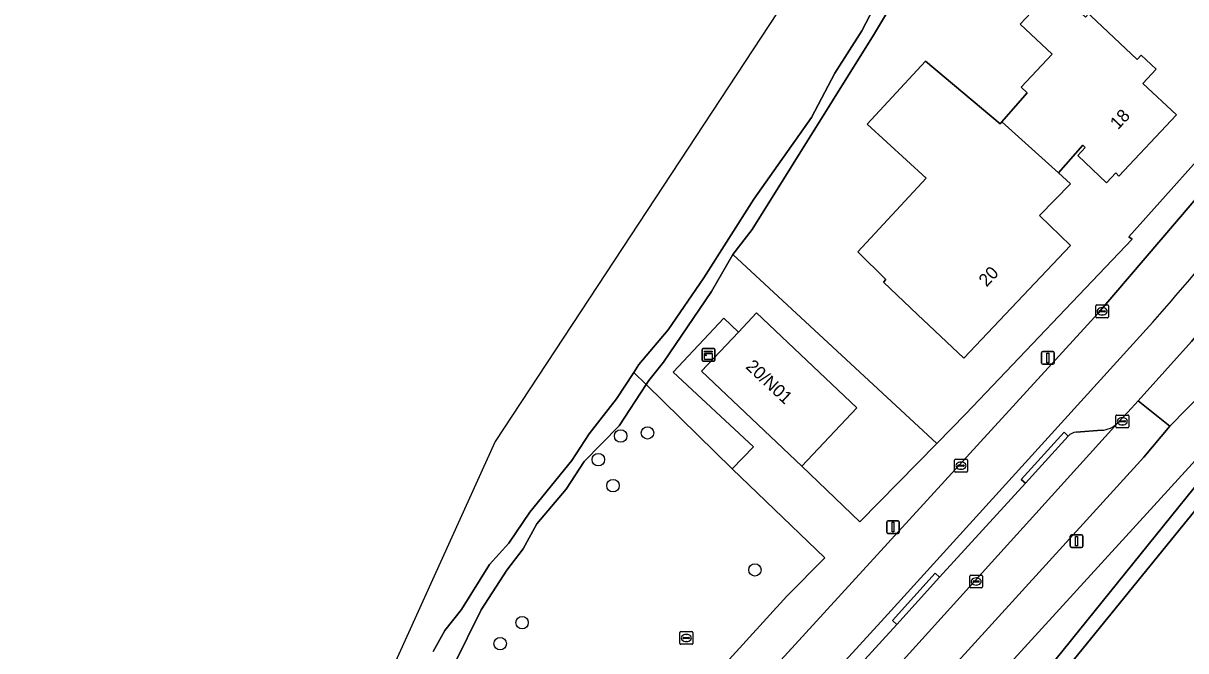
# Model space of a CAD drawing. Extents: x 161772 to 163126, y 383092 to 383917.
# Drawn here: x 161850.9 to 161942.3, y 383268.9 to 383318.3 of the extents above; entities that cross this region are included whole.
import ezdxf

# ---------------------------------------------------------------- set-up
doc = ezdxf.new("R2010")
doc.units = 0
for name, color, linetype in [('IMGEO_Berm_open', 7, 'Continuous'), ('IMGEO_Boom', 7, 'Continuous'), ('IMGEO_Erf', 7, 'Continuous'), ('IMGEO_Fietspad_gesloten', 7, 'Continuous'), ('IMGEO_Groenvoorziening', 7, 'Continuous'), ('IMGEO_Hek', 7, 'Continuous'), ('IMGEO_Kast', 7, 'Continuous'), ('IMGEO_Kolk', 7, 'Continuous'), ('IMGEO_Lichtmast', 7, 'Continuous'), ('IMGEO_Oever', 7, 'Continuous'), ('IMGEO_Pand', 7, 'Continuous'), ('IMGEO_Pand_nummerreeks', 7, 'Continuous'), ('IMGEO_Parkeervlak_open', 7, 'Continuous'), ('IMGEO_Rijbaan_lokaal_gesloten', 7, 'Continuous'), ('IMGEO_Rioolput', 7, 'Continuous'), ('IMGEO_Voetpad_halfverhard', 7, 'Continuous'), ('IMGEO_Voetpad_open', 7, 'Continuous'), ('IMGEO_Waterloop', 7, 'Continuous')]:
    doc.layers.add(name, color=color, linetype=linetype)

msp = doc.modelspace()

# ---------------------------------------------------------------- linework, layer by layer
at = {"layer": 'IMGEO_Berm_open'}
for points in [[(161936.941, 383286.844), (161937.725, 383287.694), (161938.545, 383288.593), (161942.733, 383293.261), (161946.965, 383298.168), (161951.858, 383304.076), (161955.895, 383309.039), (161956.93, 383310.332), (161955.277, 383311.727), (161955.257, 383311.744), (161958.985, 383316.324), (161961.426, 383319.531), (161961.064, 383319.803), (161964.615, 383324.66), (161964.958, 383324.39), (161966.144, 383326.081)], [(161939.704, 383294.768), (161918.598, 383271.518), (161889.95, 383240.214)], [(161891.178, 383239.989), (161919.558, 383271.008), (161919.229, 383271.314), (161922.593, 383275.04), (161922.916, 383274.718), (161929.677, 383282.101), (161929.346, 383282.406), (161932.714, 383286.12), (161933.044, 383285.816)], [(161933.657, 383286.132), (161935.675, 383286.268)]]:
    msp.add_lwpolyline(points, dxfattribs=at)
for points in [[(161933.044, 383285.816), (161932.714, 383286.12), (161929.346, 383282.406), (161929.677, 383282.101)], [(161922.916, 383274.718), (161922.593, 383275.04), (161919.229, 383271.314), (161919.558, 383271.008)]]:
    msp.add_lwpolyline(points, close=True, dxfattribs=at)
for centre, radius, start, end in [((161591.388, 383599.05), 462.506, 318.86018, 321.05072), ((161935.529, 383288.269), 2.006, 274.18246, 314.74636), ((161933.804, 383285.094), 1.048, 98.05832, 136.48367)]:
    msp.add_arc(centre, radius, start, end, dxfattribs=at)
at = {"layer": 'IMGEO_Boom'}
for centre in [(161897.856, 383285.821), (161899.96, 383286.062), (161896.094, 383283.96), (161897.255, 383281.917), (161908.41, 383275.292), (161890.104, 383271.15), (161888.379, 383269.494)]:
    msp.add_circle(centre, 0.489, dxfattribs=at)
at = {"layer": 'IMGEO_Erf'}
for points in [[(161924.879, 383329.289), (161917.722, 383317.318), (161908.185, 383302.04), (161906.674, 383300.084), (161904.997, 383297.167), (161901.213, 383291.611), (161900.058, 383290.19), (161899.854, 383289.876), (161906.619, 383283.229), (161908.3, 383284.957), (161901.974, 383290.839), (161905.957, 383295.079), (161907.106, 383293.995), (161908.521, 383295.495), (161916.425, 383288.039), (161912.104, 383283.459), (161916.662, 383279.077), (161922.701, 383285.219), (161925, 383287.557), (161938.061, 383301.283), (161937.818, 383301.48), (161946.008, 383310.656), (161948.264, 383313.526), (161954.519, 383321.774)], [(161934.812, 383318.85), (161938.454, 383315.424), (161938.769, 383315.758), (161939.954, 383314.644), (161938.912, 383313.536), (161941.548, 383311.055), (161937.034, 383306.258), (161936.778, 383306.499), (161936.057, 383305.732), (161933.79, 383307.865), (161934.388, 383308.5), (161934.191, 383308.685), (161932.283, 383306.506), (161933.226, 383305.654), (161930.788, 383303.163), (161933.215, 383300.787), (161924.825, 383291.929), (161921.195, 383295.367), (161918.509, 383297.912), (161918.702, 383298.116), (161916.489, 383300.309), (161921.863, 383306.099), (161917.248, 383310.333), (161921.833, 383315.278), (161927.696, 383310.365), (161927.822, 383310.509), (161929.823, 383312.795), (161929.343, 383313.247), (161931.775, 383315.831), (161929.259, 383318.198), (161931.93, 383321.045)]]:
    msp.add_lwpolyline(points, dxfattribs=at)
at = {"layer": 'IMGEO_Fietspad_gesloten'}
for points in [[(161953.961, 383317.758), (161942.798, 383304.121), (161935.389, 383295.477), (161886.612, 383242.159)], [(161889.95, 383240.214), (161918.598, 383271.518), (161939.704, 383294.768)]]:
    msp.add_lwpolyline(points, dxfattribs=at)
msp.add_arc((161591.388, 383599.05), 462.506, 318.86018, 321.05072, dxfattribs=at)
at = {"layer": 'IMGEO_Groenvoorziening'}
for points in [[(161886.411, 383246.323), (161910.93, 383273.227), (161913.897, 383276.251), (161906.619, 383283.229), (161899.854, 383289.876), (161897.734, 383286.618), (161894.983, 383283.813), (161893.566, 383281.629), (161891.274, 383278.907), (161890.193, 383276.947), (161888.911, 383275.275), (161886.883, 383272.166), (161884.708, 383267.756), (161883.189, 383265.632), (161882.266, 383263.994), (161881.616, 383259.978), (161879.669, 383255.592), (161877.612, 383250), (161876.974, 383248.266), (161883.313, 383242.582)], [(161920.997, 383254.575), (161919.034, 383256.173), (161924.881, 383263.332), (161926.722, 383261.652), (161947.115, 383286.904)], [(161944.99, 383286.04), (161914.219, 383252.347), (161915.758, 383251.09), (161917.095, 383249.921), (161920.997, 383254.575)]]:
    msp.add_lwpolyline(points, dxfattribs=at)
at = {"layer": 'IMGEO_Hek'}
msp.add_lwpolyline([(161906.674, 383300.084), (161922.701, 383285.219)], dxfattribs=at)
at = {"layer": 'IMGEO_Kast'}
for p, q in [((161904.336, 383292.699), (161905.177, 383292.699)), ((161905.177, 383292.699), (161904.336, 383292.699)), ((161904.261, 383291.774), (161904.261, 383292.615)), ((161904.261, 383292.615), (161904.261, 383291.774)), ((161905.261, 383292.624), (161905.261, 383291.783)), ((161905.261, 383291.783), (161905.261, 383292.624)), ((161905.186, 383291.699), (161904.345, 383291.699)), ((161904.345, 383291.699), (161905.186, 383291.699))]:
    msp.add_line(p, q, dxfattribs=at)
for points in [[(161904.456, 383292.489), (161905.056, 383292.489), (161905.056, 383292.404), (161904.456, 383292.404), (161904.456, 383292.489)], [(161904.456, 383292.314), (161905.056, 383292.314), (161905.056, 383291.825), (161904.456, 383291.825), (161904.456, 383292.314)]]:
    msp.add_lwpolyline(points, dxfattribs=at)
msp.add_circle((161904.54, 383292.163), 0.0377, dxfattribs=at)
for centre, start, end in [((161904.339, 383292.621), 92.4484, 184.28452), ((161904.339, 383292.621), 92.4484, 184.28452), ((161905.183, 383292.621), 2.4484, 94.28452), ((161905.183, 383292.621), 2.4484, 94.28452), ((161905.183, 383291.777), 272.4484, 4.28452), ((161905.183, 383291.777), 272.4484, 4.28452), ((161904.339, 383291.777), 182.4484, 274.28452), ((161904.339, 383291.777), 182.4484, 274.28452)]:
    msp.add_arc(centre, 0.0779, start, end, dxfattribs=at)
at = {"layer": 'IMGEO_Kolk'}
for p, q in [((161935.215, 383295.192), (161935.215, 383296.044)), ((161935.29, 383296.118), (161936.142, 383296.118)), ((161935.474, 383295.612), (161935.474, 383295.624)), ((161935.912, 383295.575), (161935.514, 383295.575)), ((161935.517, 383295.661), (161935.915, 383295.661)), ((161935.703, 383295.898), (161935.728, 383295.898)), ((161935.958, 383295.624), (161935.958, 383295.612)), ((161936.216, 383296.044), (161936.216, 383295.192)), ((161936.142, 383295.118), (161935.29, 383295.118)), ((161935.726, 383295.338), (161935.701, 383295.338)), ((161936.799, 383286.544), (161936.799, 383287.396)), ((161936.874, 383287.47), (161937.726, 383287.47)), ((161937.287, 383287.25), (161937.312, 383287.25)), ((161937.8, 383287.396), (161937.8, 383286.544)), ((161937.726, 383286.47), (161936.874, 383286.47)), ((161937.058, 383286.964), (161937.058, 383286.976)), ((161937.496, 383286.927), (161937.098, 383286.927)), ((161937.101, 383287.013), (161937.499, 383287.013)), ((161937.31, 383286.69), (161937.285, 383286.69)), ((161937.542, 383286.976), (161937.542, 383286.964)), ((161924.11, 383283.061), (161924.11, 383283.913)), ((161924.185, 383283.987), (161925.037, 383283.987)), ((161924.598, 383283.767), (161924.623, 383283.767)), ((161925.111, 383283.913), (161925.111, 383283.061)), ((161925.037, 383282.987), (161924.185, 383282.987)), ((161924.369, 383283.481), (161924.369, 383283.493)), ((161924.807, 383283.444), (161924.409, 383283.444)), ((161924.412, 383283.53), (161924.81, 383283.53)), ((161924.621, 383283.207), (161924.596, 383283.207)), ((161924.853, 383283.493), (161924.853, 383283.481)), ((161925.308, 383273.955), (161925.308, 383274.807)), ((161925.383, 383274.881), (161926.235, 383274.881)), ((161925.61, 383274.424), (161926.008, 383274.424)), ((161925.796, 383274.661), (161925.821, 383274.661)), ((161926.309, 383274.807), (161926.309, 383273.955)), ((161926.235, 383273.881), (161925.383, 383273.881)), ((161925.567, 383274.375), (161925.567, 383274.387)), ((161926.005, 383274.338), (161925.607, 383274.338)), ((161925.819, 383274.101), (161925.794, 383274.101)), ((161926.051, 383274.387), (161926.051, 383274.375))]:
    msp.add_line(p, q, dxfattribs=at)
for points in [[(161935.215, 383295.192), (161935.215, 383296.044)], [(161935.29, 383296.118), (161936.142, 383296.118)], [(161936.216, 383296.044), (161936.216, 383295.192)], [(161936.142, 383295.118), (161935.29, 383295.118)], [(161936.799, 383286.544), (161936.799, 383287.396)], [(161936.874, 383287.47), (161937.726, 383287.47)], [(161937.8, 383287.396), (161937.8, 383286.544)], [(161937.726, 383286.47), (161936.874, 383286.47)], [(161924.11, 383283.061), (161924.11, 383283.913)], [(161924.185, 383283.987), (161925.037, 383283.987)], [(161925.111, 383283.913), (161925.111, 383283.061)], [(161925.037, 383282.987), (161924.185, 383282.987)], [(161925.308, 383273.955), (161925.308, 383274.807)], [(161925.383, 383274.881), (161926.235, 383274.881)], [(161926.309, 383274.807), (161926.309, 383273.955)], [(161926.235, 383273.881), (161925.383, 383273.881)]]:
    msp.add_lwpolyline(points, dxfattribs=at)
for centre, radius, start, end in [((161935.292, 383296.042), 0.0765, 91.55205, 178.44795), ((161935.292, 383296.042), 0.0765, 91.55205, 178.44795), ((161935.514, 383295.621), 0.0403, 85.87752, 175.75265), ((161935.511, 383295.611), 0.0366, 178.93798, 274.71019), ((161935.915, 383295.618), 0.043, 264.86636, 352.45326), ((161935.919, 383295.623), 0.0386, 1.73085, 96.63898), ((161936.14, 383296.042), 0.0765, 1.55205, 88.44795), ((161936.14, 383296.042), 0.0765, 1.55205, 88.44795), ((161935.292, 383295.194), 0.0765, 181.55205, 268.44795), ((161935.292, 383295.194), 0.0765, 181.55205, 268.44795), ((161936.14, 383295.194), 0.0765, 271.55205, 358.44795), ((161936.14, 383295.194), 0.0765, 271.55205, 358.44795), ((161936.876, 383287.394), 0.0765, 91.55205, 178.44795), ((161936.876, 383287.394), 0.0765, 91.55205, 178.44795), ((161937.724, 383287.394), 0.0765, 1.55205, 88.44795), ((161937.724, 383287.394), 0.0765, 1.55205, 88.44795), ((161936.876, 383286.546), 0.0765, 181.55205, 268.44795), ((161936.876, 383286.546), 0.0765, 181.55205, 268.44795), ((161937.098, 383286.973), 0.0403, 85.87752, 175.75265), ((161937.095, 383286.963), 0.0366, 178.93798, 274.71019), ((161937.499, 383286.97), 0.043, 264.86636, 352.45326), ((161937.503, 383286.975), 0.0386, 1.73085, 96.63898), ((161937.724, 383286.546), 0.0765, 271.55205, 358.44795), ((161937.724, 383286.546), 0.0765, 271.55205, 358.44795), ((161924.187, 383283.911), 0.0765, 91.55205, 178.44795), ((161924.187, 383283.911), 0.0765, 91.55205, 178.44795), ((161925.035, 383283.911), 0.0765, 1.55205, 88.44795), ((161925.035, 383283.911), 0.0765, 1.55205, 88.44795), ((161924.187, 383283.063), 0.0765, 181.55205, 268.44795), ((161924.187, 383283.063), 0.0765, 181.55205, 268.44795), ((161924.409, 383283.49), 0.0403, 85.87752, 175.75265), ((161924.406, 383283.48), 0.0366, 178.93798, 274.71019), ((161924.81, 383283.487), 0.043, 264.86636, 352.45326), ((161924.814, 383283.492), 0.0386, 1.73085, 96.63898), ((161925.035, 383283.063), 0.0765, 271.55205, 358.44795), ((161925.035, 383283.063), 0.0765, 271.55205, 358.44795), ((161925.385, 383274.805), 0.0765, 91.55205, 178.44795), ((161925.385, 383274.805), 0.0765, 91.55205, 178.44795), ((161925.607, 383274.384), 0.0403, 85.87752, 175.75265), ((161926.012, 383274.386), 0.0386, 1.73085, 96.63898), ((161926.233, 383274.805), 0.0765, 1.55205, 88.44795), ((161926.233, 383274.805), 0.0765, 1.55205, 88.44795), ((161925.385, 383273.957), 0.0765, 181.55205, 268.44795), ((161925.385, 383273.957), 0.0765, 181.55205, 268.44795), ((161925.604, 383274.374), 0.0366, 178.93798, 274.71019), ((161926.008, 383274.381), 0.043, 264.86636, 352.45326), ((161926.233, 383273.957), 0.0765, 271.55205, 358.44795), ((161926.233, 383273.957), 0.0765, 271.55205, 358.44795)]:
    msp.add_arc(centre, radius, start, end, dxfattribs=at)
for centre, major_axis, ratio, start_param, end_param in [((161935.702, 383295.618), (-0.387, 0.002), 0.722429, 4.712389, 7.853982), ((161935.727, 383295.618), (-0.39, 0.002), 0.717154, 1.570796, 4.712389), ((161937.286, 383286.97), (-0.387, 0.002), 0.722429, 4.712389, 7.853982), ((161937.311, 383286.97), (-0.39, 0.002), 0.717154, 1.570796, 4.712389), ((161924.597, 383283.487), (-0.387, 0.002), 0.722429, 4.712389, 7.853982), ((161924.622, 383283.487), (-0.39, 0.002), 0.717154, 1.570796, 4.712389), ((161925.795, 383274.381), (-0.387, 0.002), 0.722429, 4.712389, 7.853982), ((161925.82, 383274.381), (-0.39, 0.002), 0.717154, 1.570796, 4.712389)]:
    msp.add_ellipse(centre, major_axis=major_axis, ratio=ratio, start_param=start_param, end_param=end_param, dxfattribs=at)
at = {"layer": 'IMGEO_Lichtmast'}
for p, q in [((161930.945, 383291.556), (161930.945, 383292.356)), ((161930.945, 383292.356), (161930.945, 383291.556)), ((161931.045, 383292.456), (161931.835, 383292.456)), ((161931.835, 383292.456), (161931.045, 383292.456)), ((161931.935, 383292.356), (161931.935, 383291.556)), ((161931.935, 383291.556), (161931.935, 383292.356)), ((161931.835, 383291.456), (161931.045, 383291.456)), ((161931.045, 383291.456), (161931.835, 383291.456)), ((161918.771, 383278.262), (161918.771, 383279.062)), ((161918.771, 383279.062), (161918.771, 383278.262)), ((161918.871, 383279.162), (161919.661, 383279.162)), ((161919.661, 383279.162), (161918.871, 383279.162)), ((161919.761, 383279.062), (161919.761, 383278.262)), ((161919.761, 383278.262), (161919.761, 383279.062)), ((161919.661, 383278.162), (161918.871, 383278.162)), ((161918.871, 383278.162), (161919.661, 383278.162)), ((161933.208, 383277.15), (161933.208, 383277.95)), ((161933.208, 383277.95), (161933.208, 383277.15)), ((161933.308, 383278.05), (161934.098, 383278.05)), ((161934.098, 383278.05), (161933.308, 383278.05)), ((161934.198, 383277.95), (161934.198, 383277.15)), ((161934.198, 383277.15), (161934.198, 383277.95)), ((161934.098, 383277.05), (161933.308, 383277.05)), ((161933.308, 383277.05), (161934.098, 383277.05))]:
    msp.add_line(p, q, dxfattribs=at)
for points in [[(161931.365, 383292.331), (161931.515, 383292.331), (161931.515, 383291.581), (161931.365, 383291.581), (161931.365, 383292.331)], [(161919.191, 383279.037), (161919.341, 383279.037), (161919.341, 383278.287), (161919.191, 383278.287), (161919.191, 383279.037)], [(161933.628, 383277.925), (161933.778, 383277.925), (161933.778, 383277.175), (161933.628, 383277.175), (161933.628, 383277.925)]]:
    msp.add_lwpolyline(points, dxfattribs=at)
for centre, start, end in [((161931.045, 383292.356), 90, 180), ((161931.045, 383292.356), 90, 180), ((161931.835, 383292.356), 0, 90), ((161931.835, 383292.356), 360, 90), ((161931.045, 383291.556), 180, 270), ((161931.045, 383291.556), 180, 270), ((161931.835, 383291.556), 270, 0), ((161931.835, 383291.556), 270, 0), ((161918.871, 383279.062), 90, 180), ((161918.871, 383279.062), 90, 180), ((161919.661, 383279.062), 0, 90), ((161919.661, 383279.062), 360, 90), ((161918.871, 383278.262), 180, 270), ((161918.871, 383278.262), 180, 270), ((161919.661, 383278.262), 270, 0), ((161919.661, 383278.262), 270, 0), ((161933.308, 383277.95), 90, 180), ((161933.308, 383277.95), 90, 180), ((161933.308, 383277.15), 180, 270), ((161933.308, 383277.15), 180, 270), ((161934.098, 383277.95), 0, 90), ((161934.098, 383277.95), 360, 90), ((161934.098, 383277.15), 270, 0), ((161934.098, 383277.15), 270, 0)]:
    msp.add_arc(centre, 0.1, start, end, dxfattribs=at)
at = {"layer": 'IMGEO_Oever'}
msp.add_lwpolyline([(161908.185, 383302.04), (161917.722, 383317.318), (161924.879, 383329.289), (161925.946, 383331.543), (161924.968, 383331.928), (161924.309, 383330.433), (161920.581, 383324.286), (161919.3, 383322.473), (161916.819, 383317.679), (161914.701, 383314.331), (161912.867, 383310.862), (161908.313, 383304.448), (161904.396, 383298.261), (161901.588, 383294.174), (161899.29, 383291.435), (161898.889, 383290.821), (161899.854, 383289.876), (161900.058, 383290.19), (161901.213, 383291.611), (161904.997, 383297.167), (161906.674, 383300.084)], close=True, dxfattribs=at)
msp.add_lwpolyline([(161884.708, 383267.756), (161886.883, 383272.166), (161888.911, 383275.275), (161890.193, 383276.947), (161891.274, 383278.907), (161893.566, 383281.629), (161894.983, 383283.813), (161897.734, 383286.618), (161899.854, 383289.876), (161898.889, 383290.821), (161897.534, 383288.746), (161895.382, 383285.996), (161894.016, 383283.892), (161890.705, 383279.832), (161889.05, 383277.406), (161887.548, 383275.712), (161885.333, 383272.181), (161884.04, 383270.529), (161883.112, 383268.88)], dxfattribs=at)
at = {"layer": 'IMGEO_Pand'}
for points in [[(161932.283, 383306.506), (161934.191, 383308.685), (161934.388, 383308.5), (161933.79, 383307.865), (161936.057, 383305.732), (161936.778, 383306.499), (161937.034, 383306.258), (161941.548, 383311.055), (161938.912, 383313.536), (161939.954, 383314.644), (161938.769, 383315.758), (161938.454, 383315.424), (161934.812, 383318.85), (161934.651, 383319.002), (161934.41, 383318.746), (161931.93, 383321.045), (161929.259, 383318.198), (161931.775, 383315.831), (161929.343, 383313.247), (161929.823, 383312.795), (161927.822, 383310.509)], [(161930.788, 383303.163), (161933.226, 383305.654), (161932.283, 383306.506), (161927.822, 383310.509), (161927.696, 383310.365), (161921.833, 383315.278), (161917.248, 383310.333), (161921.863, 383306.099), (161916.489, 383300.309), (161918.702, 383298.116), (161918.509, 383297.912), (161921.195, 383295.367), (161924.825, 383291.929), (161933.215, 383300.787)], [(161912.104, 383283.459), (161916.425, 383288.039), (161908.521, 383295.495), (161907.106, 383293.995), (161904.201, 383290.915)]]:
    msp.add_lwpolyline(points, close=True, dxfattribs=at)
msp.add_lwpolyline([(161955.86, 383268.264), (161962.128, 383275.94), (161960.12, 383277.564), (161956.679, 383280.347), (161958.125, 383282.154), (161958.256, 383282.318), (161955.767, 383284.327), (161955.635, 383284.17), (161954.187, 383282.446), (161950.745, 383285.25), (161948.835, 383286.806), (161948.692, 383286.922), (161926.928, 383260.179)], dxfattribs=at)
at = {"layer": 'IMGEO_Parkeervlak_open'}
for points in [[(161892.025, 383237.199), (161936.941, 383286.844)], [(161933.044, 383285.816), (161929.677, 383282.101), (161922.916, 383274.718), (161919.558, 383271.008), (161891.178, 383239.989)], [(161935.675, 383286.268), (161933.657, 383286.132)]]:
    msp.add_lwpolyline(points, dxfattribs=at)
for centre, radius, start, end in [((161935.529, 383288.269), 2.006, 274.18246, 314.74636), ((161933.804, 383285.094), 1.048, 98.05832, 136.48367)]:
    msp.add_arc(centre, radius, start, end, dxfattribs=at)
at = {"layer": 'IMGEO_Rijbaan_lokaal_gesloten'}
for points in [[(161956.302, 383304.313), (161960.136, 383308.977), (161960.862, 383309.86), (161958.255, 383311.968), (161956.93, 383310.332), (161955.895, 383309.039), (161951.858, 383304.076), (161946.965, 383298.168), (161942.733, 383293.261), (161938.545, 383288.593), (161941.028, 383286.586), (161943.672, 383289.284)], [(161890.056, 383230.375), (161894.115, 383235.022), (161925.176, 383268.972), (161938.996, 383284.148), (161941.028, 383286.586), (161938.545, 383288.593), (161937.725, 383287.694), (161936.941, 383286.844), (161892.025, 383237.199)]]:
    msp.add_lwpolyline(points, dxfattribs=at)
at = {"layer": 'IMGEO_Rioolput'}
for p, q in [((161902.517, 383269.518), (161902.517, 383270.37)), ((161902.592, 383270.444), (161903.444, 383270.444)), ((161902.776, 383269.938), (161902.776, 383269.95)), ((161903.214, 383269.901), (161902.816, 383269.901)), ((161902.819, 383269.987), (161903.217, 383269.987)), ((161903.005, 383270.224), (161903.03, 383270.224)), ((161903.26, 383269.95), (161903.26, 383269.938)), ((161903.518, 383270.37), (161903.518, 383269.518)), ((161903.444, 383269.444), (161902.592, 383269.444)), ((161903.028, 383269.664), (161903.003, 383269.664))]:
    msp.add_line(p, q, dxfattribs=at)
for points in [[(161902.517, 383269.518), (161902.517, 383270.37)], [(161902.592, 383270.444), (161903.444, 383270.444)], [(161903.518, 383270.37), (161903.518, 383269.518)], [(161903.444, 383269.444), (161902.592, 383269.444)]]:
    msp.add_lwpolyline(points, dxfattribs=at)
for centre, radius, start, end in [((161902.594, 383270.368), 0.0765, 91.55205, 178.44795), ((161902.594, 383270.368), 0.0765, 91.55205, 178.44795), ((161902.816, 383269.947), 0.0403, 85.87752, 175.75265), ((161902.813, 383269.937), 0.0366, 178.93798, 274.71019), ((161903.217, 383269.944), 0.043, 264.86636, 352.45326), ((161903.221, 383269.949), 0.0386, 1.73085, 96.63898), ((161903.442, 383270.368), 0.0765, 1.55205, 88.44795), ((161903.442, 383270.368), 0.0765, 1.55205, 88.44795), ((161902.594, 383269.52), 0.0765, 181.55205, 268.44795), ((161902.594, 383269.52), 0.0765, 181.55205, 268.44795), ((161903.442, 383269.52), 0.0765, 271.55205, 358.44795), ((161903.442, 383269.52), 0.0765, 271.55205, 358.44795)]:
    msp.add_arc(centre, radius, start, end, dxfattribs=at)
for centre, major_axis, ratio, start_param, end_param in [((161903.004, 383269.944), (-0.387, 0.002), 0.722429, 4.712389, 7.853982), ((161903.029, 383269.944), (-0.39, 0.002), 0.717154, 1.570796, 4.712389)]:
    msp.add_ellipse(centre, major_axis=major_axis, ratio=ratio, start_param=start_param, end_param=end_param, dxfattribs=at)
at = {"layer": 'IMGEO_Voetpad_halfverhard'}
msp.add_lwpolyline([(161948.692, 383286.922), (161947.115, 383286.904), (161926.722, 383261.652), (161924.881, 383263.332), (161919.034, 383256.173), (161920.997, 383254.575), (161917.095, 383249.921), (161916.403, 383249.095), (161917.31, 383248.385), (161918.629, 383250), (161920.31, 383252.058), (161922.56, 383254.822), (161922.433, 383255.394), (161922.368, 383256.269), (161922.513, 383257.114), (161922.87, 383257.998), (161923.38, 383258.622), (161923.996, 383259.376), (161924.808, 383259.886), (161925.396, 383260.247), (161926.113, 383260.316), (161926.928, 383260.179)], close=True, dxfattribs=at)
at = {"layer": 'IMGEO_Voetpad_open'}
for points in [[(161954.519, 383321.774), (161948.264, 383313.526), (161946.008, 383310.656), (161937.818, 383301.48), (161938.061, 383301.283), (161925, 383287.557), (161922.701, 383285.219), (161916.662, 383279.077), (161912.104, 383283.459), (161904.201, 383290.915), (161907.106, 383293.995), (161905.957, 383295.079), (161901.974, 383290.839), (161908.3, 383284.957), (161906.619, 383283.229), (161913.897, 383276.251), (161910.93, 383273.227), (161886.411, 383246.323)], [(161886.612, 383242.159), (161935.389, 383295.477), (161942.798, 383304.121), (161953.961, 383317.758)], [(161943.672, 383289.284), (161941.028, 383286.586), (161938.996, 383284.148), (161925.176, 383268.972), (161894.115, 383235.022), (161890.056, 383230.375)], [(161889.361, 383224.53), (161893.362, 383229.411), (161895.999, 383232.397), (161910.307, 383248.064), (161914.219, 383252.347), (161944.99, 383286.04)]]:
    msp.add_lwpolyline(points, dxfattribs=at)
at = {"layer": 'IMGEO_Waterloop'}
for points in [[(161776.244, 383589.61), (161778.284, 383505.12), (161790.6, 383486.558), (161849.991, 383470.088), (161903.645, 383424.673), (161918.25, 383394.855), (161926.064, 383360.514), (161921.083, 383335.736), (161896.051, 383297.648), (161887.994, 383285.389), (161863.101, 383230.489), (161841.142, 383179.277)], [(161883.112, 383268.88), (161884.04, 383270.529), (161885.333, 383272.181), (161887.548, 383275.712), (161889.05, 383277.406), (161890.705, 383279.832), (161894.016, 383283.892), (161895.382, 383285.996), (161897.534, 383288.746), (161898.889, 383290.821), (161899.29, 383291.435), (161901.588, 383294.174), (161904.396, 383298.261), (161908.313, 383304.448), (161912.867, 383310.862), (161914.701, 383314.331), (161916.819, 383317.679), (161919.3, 383322.473)]]:
    msp.add_lwpolyline(points, dxfattribs=at)

# ---------------------------------------------------------------- texts
at = {"layer": 'IMGEO_Pand_nummerreeks'}
for s, rotation, p in [('18', 46.74092, (161936.954, 383309.851)), ('20', 46.55282, (161926.625, 383297.493)), ('20/N01', 317.00253, (161907.62, 383291.195))]:
    msp.add_text(s, height=1, rotation=rotation, dxfattribs=at).set_placement(p)

doc.saveas('drawing.dxf')
